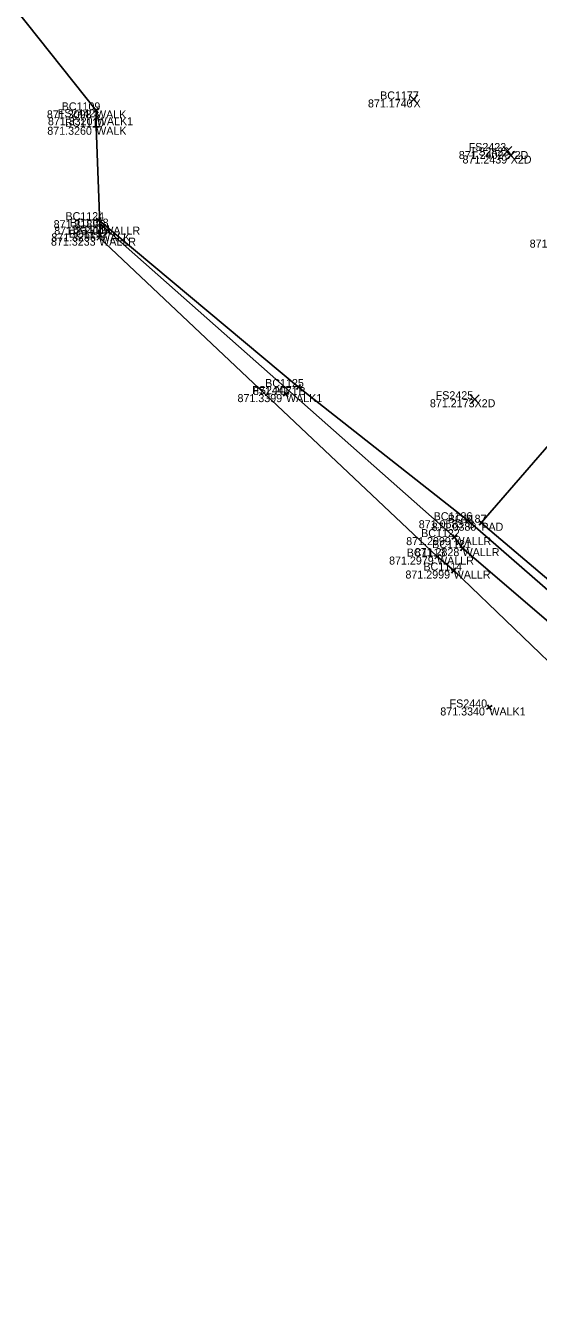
# Model space of a CAD drawing. Extents: x 1479425 to 1480294, y 379351 to 380102.
# Drawn here: x 1479564.08 to 1479567.93, y 379932.73 to 379942.32 of the extents above; entities that cross this region are included whole.
import ezdxf

# ---------------------------------------------------------------- set-up
doc = ezdxf.new("R2010")
doc.units = 0
for name, color, linetype in [('PV_X_Walk', 7, 'Continuous'), ('RD_X_Concrete_Pad', 7, 'Continuous'), ('RD_X_Wall', 7, 'Continuous'), ('SV_X_Break_Lines', 7, 'Continuous'), ('SV_X_Random_Point', 7, 'Continuous'), ('SV_X_Shot_Marker', 7, 'Continuous'), ('SV_X_Text_Comment', 7, 'Continuous'), ('SV_X_Text_Elevation', 7, 'Continuous'), ('SV_X_Text_Name', 7, 'Continuous')]:
    doc.layers.add(name, color=color, linetype=linetype)

msp = doc.modelspace()

# ---------------------------------------------------------------- linework, layer by layer
at = {"layer": 'PV_X_Walk'}
msp.add_lwpolyline([(1479558.1533, 379948.6891), (1479558.2173, 379948.6136), (1479559.9758, 379946.7326), (1479561.3946, 379945.1834), (1479561.4717, 379945.0963), (1479563.6557, 379942.8794), (1479564.6103, 379941.6807), (1479564.6114, 379941.5578), (1479564.6404, 379940.759)], dxfattribs=at)
at = {"layer": 'RD_X_Concrete_Pad'}
msp.add_lwpolyline([(1479568.9885, 379937.3268), (1479571.5704, 379940.3025), (1479570.1014, 379941.5882), (1479567.4997, 379938.5893)], close=True, dxfattribs=at)
at = {"layer": 'RD_X_Wall'}
msp.add_lwpolyline([(1479564.6337, 379940.7266), (1479567.168, 379938.3359), (1479567.2924, 379938.2311), (1479568.6502, 379936.9271), (1479568.7466, 379936.8724), (1479573.0444, 379932.7293), (1479572.9032, 379933.627), (1479568.8936, 379937.0738), (1479568.8238, 379937.1435), (1479567.359, 379938.3988), (1479567.2981, 379938.4814), (1479564.6647, 379940.8093)], dxfattribs=at)
at = {"layer": 'SV_X_Break_Lines'}
msp.add_lwpolyline([(1479564.6308, 379940.8576), (1479566.1289, 379939.6067), (1479567.3964, 379938.6081), (1479569.0046, 379937.2067), (1479570.7003, 379935.7642), (1479572.8418, 379933.8454)], dxfattribs=at)
at = {"layer": 'SV_X_Random_Point'}
for p, q in [((1479566.9578, 379941.7294), (1479567.0244, 379941.7962)), ((1479566.9578, 379941.7962), (1479567.0244, 379941.7294)), ((1479567.6627, 379941.3426), (1479567.7293, 379941.4094)), ((1479567.6627, 379941.4094), (1479567.7293, 379941.3426)), ((1479567.6867, 379941.3089), (1479567.7533, 379941.3757)), ((1479567.6867, 379941.3757), (1479567.7533, 379941.3089)), ((1479567.4157, 379939.4818), (1479567.4823, 379939.5486)), ((1479567.4157, 379939.5486), (1479567.4823, 379939.4818))]:
    msp.add_line(p, q, dxfattribs=at)
at = {"layer": 'SV_X_Shot_Marker'}
for p, q in [((1479564.6299, 379941.6963), (1479564.5907, 379941.6651)), ((1479564.5947, 379941.7003), (1479564.6259, 379941.6612)), ((1479564.5974, 379941.6129), (1479564.6346, 379941.6462)), ((1479564.6327, 379941.6109), (1479564.5993, 379941.6482)), ((1479564.6103, 379941.6807), (1479564.6103, 379941.6807)), ((1479564.6364, 379941.558), (1479564.5864, 379941.5576)), ((1479564.6112, 379941.5828), (1479564.6116, 379941.5328)), ((1479564.6114, 379941.5578), (1479564.6114, 379941.5578)), ((1479564.616, 379941.6295), (1479564.616, 379941.6295)), ((1479564.6468, 379940.8768), (1479564.6148, 379940.8384)), ((1479564.6116, 379940.8736), (1479564.65, 379940.8416)), ((1479564.6308, 379940.8576), (1479564.6308, 379940.8576)), ((1479564.6395, 379940.784), (1479564.6413, 379940.734)), ((1479564.6834, 379940.7928), (1479564.646, 379940.8259)), ((1479564.6481, 379940.7906), (1479564.6813, 379940.8281)), ((1479564.6647, 379940.8093), (1479564.6647, 379940.8093)), ((1479564.6654, 379940.7599), (1479564.6154, 379940.7581)), ((1479564.6155, 379940.7438), (1479564.6519, 379940.7095)), ((1479564.6509, 379940.7448), (1479564.6165, 379940.7084)), ((1479564.6337, 379940.7266), (1479564.6337, 379940.7266)), ((1479564.6404, 379940.759), (1479564.6404, 379940.759)), ((1479566.0144, 379939.5395), (1479566.0556, 379939.5677)), ((1479566.0491, 379939.533), (1479566.0209, 379939.5743)), ((1479566.035, 379939.5536), (1479566.035, 379939.5536)), ((1479566.1097, 379939.6227), (1479566.1481, 379939.5907)), ((1479566.1449, 379939.6259), (1479566.1129, 379939.5875)), ((1479566.1289, 379939.6067), (1479566.1289, 379939.6067)), ((1479567.3768, 379938.6236), (1479567.416, 379938.5926)), ((1479567.4119, 379938.6278), (1479567.3809, 379938.5885)), ((1479567.3964, 379938.6081), (1479567.3964, 379938.6081)), ((1479567.5186, 379938.5729), (1479567.4808, 379938.6057)), ((1479567.5161, 379938.6082), (1479567.4833, 379938.5704)), ((1479567.4997, 379938.5893), (1479567.4997, 379938.5893)), ((1479567.278, 379938.4666), (1479567.3182, 379938.4963)), ((1479567.3129, 379938.4613), (1479567.2833, 379938.5015)), ((1479567.2981, 379938.4814), (1479567.2981, 379938.4814)), ((1479567.378, 379938.3826), (1479567.34, 379938.4151)), ((1479567.3427, 379938.3798), (1479567.3753, 379938.4178)), ((1479567.359, 379938.3988), (1479567.359, 379938.3988)), ((1479567.1498, 379938.3531), (1479567.1862, 379938.3188)), ((1479567.1852, 379938.3541), (1479567.1508, 379938.3177)), ((1479567.168, 379938.3359), (1479567.168, 379938.3359)), ((1479567.2733, 379938.2472), (1479567.3115, 379938.215)), ((1479567.3085, 379938.2502), (1479567.2763, 379938.212)), ((1479567.2924, 379938.2311), (1479567.2924, 379938.2311)), ((1479567.539, 379937.1909), (1479567.581, 379937.2181)), ((1479567.5736, 379937.1836), (1479567.5464, 379937.2255)), ((1479567.56, 379937.2045), (1479567.56, 379937.2045))]:
    msp.add_line(p, q, dxfattribs=at)

# ---------------------------------------------------------------- texts
at = {"layer": 'SV_X_Text_Comment'}
for s, p in [('X', (1479566.9911, 379941.7028)), ('WALK', (1479564.6103, 379941.6207)), ('WALK', (1479564.6114, 379941.4978)), ('WALK1', (1479564.616, 379941.5695)), ('X2D', (1479567.696, 379941.316)), ('X2D', (1479567.72, 379941.2823)), ('B', (1479564.6308, 379940.7976)), ('WALLR', (1479564.6647, 379940.7493)), ('WALLR', (1479564.6337, 379940.6666)), ('WALK', (1479564.6404, 379940.699)), ('WALK1', (1479566.035, 379939.4936)), ('B', (1479566.1289, 379939.5467)), ('X2D', (1479567.449, 379939.4552)), ('B', (1479567.3964, 379938.5481)), ('PAD', (1479567.4997, 379938.5293)), ('WALLR', (1479567.2981, 379938.4214)), ('WALLR', (1479567.359, 379938.3388)), ('WALLR', (1479567.168, 379938.2759)), ('WALLR', (1479567.2924, 379938.1711)), ('WALK1', (1479567.56, 379937.1445))]:
    msp.add_text(s, height=0.06, dxfattribs=at).set_placement(p)
at = {"layer": 'SV_X_Text_Elevation'}
for s, p in [('871.1740', (1479566.6496, 379941.7028)), ('871.3098', (1479564.2418, 379941.6207)), ('871.3260', (1479564.2448, 379941.4978)), ('871.3320', (1479564.2494, 379941.5695)), ('871.2402', (1479567.3309, 379941.316)), ('871.2439', (1479567.3586, 379941.2823)), ('871.3189', (1479564.2926, 379940.7976)), ('871.3340', (1479564.2967, 379940.7493)), ('871.3233', (1479564.2723, 379940.6666)), ('871.3296', (1479564.2753, 379940.699)), ('871.0528', (1479567.8622, 379940.6518)), ('871.3399', (1479565.6713, 379939.4936)), ('871.2071', (1479565.7873, 379939.5467)), ('871.2173', (1479567.1141, 379939.4552)), ('871.0583', (1479567.0303, 379938.5481)), ('871.0380', (1479567.1275, 379938.5293)), ('871.2999', (1479566.9363, 379938.4214)), ('871.2828', (1479567, 379938.3388)), ('871.2979', (1479566.808, 379938.2759)), ('871.2999', (1479566.9306, 379938.1711)), ('871.3340', (1479567.192, 379937.1445))]:
    msp.add_text(s, height=0.06, dxfattribs=at).set_placement(p)
at = {"layer": 'SV_X_Text_Name'}
for s, p in [('BC1109', (1479564.3529, 379941.6807)), ('BC1177', (1479566.7408, 379941.7628)), ('FS2442', (1479564.3236, 379941.6295)), ('BC1110', (1479564.3786, 379941.5578)), ('FS2422', (1479567.405, 379941.376)), ('FS2423', (1479567.4285, 379941.3423)), ('BC1124', (1479564.381, 379940.8576)), ('BC1112', (1479564.4066, 379940.7266)), ('BC1123', (1479564.4144, 379940.8093)), ('BC1111', (1479564.4353, 379940.759)), ('BC1125', (1479565.8786, 379939.6067)), ('FS2441', (1479565.7821, 379939.5536)), ('FS2425', (1479567.1575, 379939.5152)), ('BC1126', (1479567.1423, 379938.6081)), ('BC1187', (1479567.2484, 379938.5893)), ('BC1122', (1479567.0483, 379938.4814)), ('BC1113', (1479566.9404, 379938.3359)), ('BC1121', (1479567.1312, 379938.3988)), ('BC1114', (1479567.0653, 379938.2311)), ('FS2440', (1479567.2619, 379937.2045))]:
    msp.add_text(s, height=0.06, dxfattribs=at).set_placement(p)

doc.saveas('drawing.dxf')
